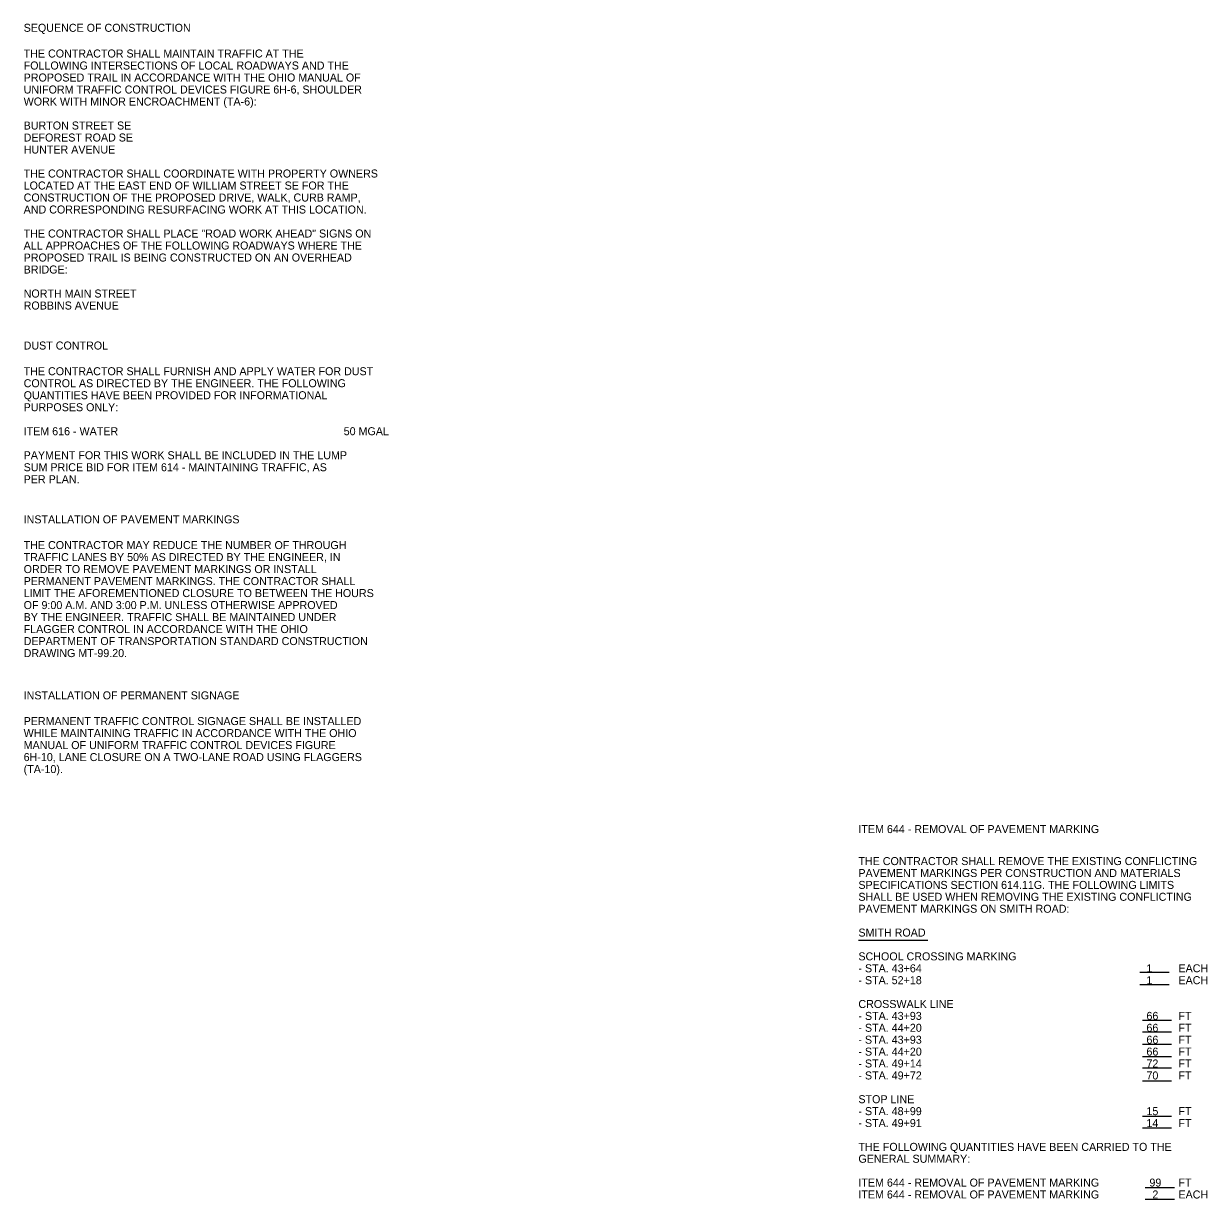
# Model space of a CAD drawing. Extents: x -39.4 to 36.9, y -12.9 to 28.
# Drawn here: x -39.35 to -18.64, y -12.34 to 8.24 of the extents above; entities that cross this region are included whole.
import ezdxf

# ---------------------------------------------------------------- set-up
doc = ezdxf.new("R2010")
doc.units = 0
for name, color, linetype in [('PM_P_Text', 7, 'Continuous'), ('SH_Text', 7, 'Continuous'), ('TX_P_1', 7, 'Continuous')]:
    doc.layers.add(name, color=color, linetype=linetype)

msp = doc.modelspace()

# ---------------------------------------------------------------- linework, layer by layer
at = {"layer": 'SH_Text'}
for p, q in [((-24.746, -7.803), (-23.532, -7.803)), ((-19.821, -8.364), (-19.31, -8.364)), ((-19.821, -8.577), (-19.31, -8.577)), ((-19.777, -9.2), (-19.266, -9.2)), ((-19.777, -9.409), (-19.266, -9.409)), ((-19.777, -9.621), (-19.266, -9.621)), ((-19.777, -9.841), (-19.266, -9.841)), ((-19.777, -10.039), (-19.266, -10.039)), ((-19.777, -10.263), (-19.266, -10.263)), ((-19.777, -10.881), (-19.266, -10.881)), ((-19.777, -11.088), (-19.266, -11.088)), ((-19.728, -12.131), (-19.217, -12.131)), ((-19.728, -12.338), (-19.217, -12.338))]:
    msp.add_line(p, q, dxfattribs=at)

# ---------------------------------------------------------------- texts
at = {"layer": 'PM_P_Text'}
for s, p in [('THE CONTRACTOR SHALL REMOVE THE EXISTING CONFLICTING', (-24.746, -6.489)), ('PAVEMENT MARKINGS PER CONSTRUCTION AND MATERIALS', (-24.746, -6.698)), ('SPECIFICATIONS SECTION 614.11G. THE FOLLOWING LIMITS', (-24.746, -6.906)), ('SHALL BE USED WHEN REMOVING THE EXISTING CONFLICTING', (-24.746, -7.114)), ('PAVEMENT MARKINGS ON SMITH ROAD:', (-24.746, -7.323)), ('SMITH ROAD', (-24.746, -7.74)), ('SCHOOL CROSSING MARKING', (-24.746, -8.156)), ('- STA. 43+64', (-24.746, -8.365)), ('1 ', (-19.706, -8.365)), ('EACH', (-19.146, -8.365)), ('- STA. 52+18', (-24.746, -8.573)), ('1 ', (-19.706, -8.573)), ('EACH', (-19.146, -8.573)), ('CROSSWALK LINE', (-24.746, -8.99)), ('- STA. 43+93', (-24.746, -9.198)), ('66 ', (-19.706, -9.198)), ('FT', (-19.146, -9.198)), ('- STA. 44+20', (-24.746, -9.406)), ('66', (-19.706, -9.406)), ('FT', (-19.146, -9.406)), ('- STA. 43+93', (-24.746, -9.615)), ('66 ', (-19.706, -9.615)), ('FT', (-19.146, -9.615)), ('- STA. 44+20', (-24.746, -9.823)), ('66 ', (-19.706, -9.823)), ('FT', (-19.146, -9.823)), ('- STA. 49+14 ', (-24.746, -10.031)), ('72', (-19.706, -10.031)), ('FT', (-19.146, -10.031)), ('- STA. 49+72', (-24.746, -10.24)), ('70 ', (-19.706, -10.24)), ('FT', (-19.146, -10.24)), ('STOP LINE', (-24.746, -10.656)), ('- STA. 48+99', (-24.746, -10.865)), ('15 ', (-19.706, -10.865)), ('FT', (-19.146, -10.865)), ('- STA. 49+91', (-24.746, -11.073)), ('14 ', (-19.706, -11.073)), ('FT', (-19.146, -11.073)), ('THE FOLLOWING QUANTITIES HAVE BEEN CARRIED TO THE ', (-24.746, -11.49)), ('GENERAL SUMMARY:', (-24.746, -11.698)), ('ITEM 644 - REMOVAL OF PAVEMENT MARKING', (-24.746, -12.115)), (' 99', (-19.706, -12.115)), ('FT', (-19.146, -12.115)), ('ITEM 644 - REMOVAL OF PAVEMENT MARKING', (-24.746, -12.323)), ('  2', (-19.706, -12.323)), ('EACH', (-19.146, -12.323))]:
    msp.add_text(s, height=0.14, dxfattribs=at).set_placement(p)
at = {"layer": 'SH_Text'}
msp.add_text('ITEM 644 - REMOVAL OF PAVEMENT MARKING', height=0.14, dxfattribs=at).set_placement((-24.746, -5.929))
at = {"layer": 'TX_P_1'}
for s, p in [('SEQUENCE OF CONSTRUCTION', (-39.352, 8.093)), ('THE CONTRACTOR SHALL MAINTAIN TRAFFIC AT THE ', (-39.352, 7.643)), ('FOLLOWING INTERSECTIONS OF LOCAL ROADWAYS AND THE ', (-39.352, 7.433)), ('PROPOSED TRAIL IN ACCORDANCE WITH THE OHIO MANUAL OF ', (-39.352, 7.223)), ('UNIFORM TRAFFIC CONTROL DEVICES FIGURE 6H-6, SHOULDER ', (-39.352, 7.013)), ('WORK WITH MINOR ENCROACHMENT (TA-6):', (-39.352, 6.803)), ('BURTON STREET SE', (-39.352, 6.383)), ('DEFOREST ROAD SE', (-39.352, 6.173)), ('HUNTER AVENUE', (-39.352, 5.963)), ('THE CONTRACTOR SHALL COORDINATE WITH PROPERTY OWNERS ', (-39.352, 5.543)), ('LOCATED AT THE EAST END OF WILLIAM STREET SE FOR THE ', (-39.352, 5.333)), ('CONSTRUCTION OF THE PROPOSED DRIVE, WALK, CURB RAMP, ', (-39.352, 5.123)), ('AND CORRESPONDING RESURFACING WORK AT THIS LOCATION.', (-39.352, 4.913)), ('THE CONTRACTOR SHALL PLACE "ROAD WORK AHEAD" SIGNS ON ', (-39.352, 4.493)), ('ALL APPROACHES OF THE FOLLOWING ROADWAYS WHERE THE ', (-39.352, 4.283)), ('PROPOSED TRAIL IS BEING CONSTRUCTED ON AN OVERHEAD ', (-39.352, 4.073)), ('BRIDGE:', (-39.352, 3.863)), ('NORTH MAIN STREET', (-39.352, 3.443)), ('ROBBINS AVENUE', (-39.352, 3.233)), ('DUST CONTROL', (-39.352, 2.533)), ('THE CONTRACTOR SHALL FURNISH AND APPLY WATER FOR DUST ', (-39.352, 2.083)), ('CONTROL AS DIRECTED BY THE ENGINEER. THE FOLLOWING ', (-39.352, 1.873)), ('QUANTITIES HAVE BEEN PROVIDED FOR INFORMATIONAL ', (-39.352, 1.663)), ('PURPOSES ONLY:', (-39.352, 1.453)), ('ITEM 616 - WATER', (-39.352, 1.033)), ('50 MGAL', (-33.752, 1.033)), ('PAYMENT FOR THIS WORK SHALL BE INCLUDED IN THE LUMP ', (-39.352, 0.613)), ('SUM PRICE BID FOR ITEM 614 - MAINTAINING TRAFFIC, AS ', (-39.352, 0.403)), ('PER PLAN.', (-39.352, 0.193)), ('INSTALLATION OF PAVEMENT MARKINGS', (-39.352, -0.509)), ('THE CONTRACTOR MAY REDUCE THE NUMBER OF THROUGH ', (-39.352, -0.959)), ('TRAFFIC LANES BY 50% AS DIRECTED BY THE ENGINEER, IN ', (-39.352, -1.169)), ('ORDER TO REMOVE PAVEMENT MARKINGS OR INSTALL ', (-39.352, -1.379)), ('PERMANENT PAVEMENT MARKINGS. THE CONTRACTOR SHALL ', (-39.352, -1.589)), ('LIMIT THE AFOREMENTIONED CLOSURE TO BETWEEN THE HOURS ', (-39.352, -1.799)), ('OF 9:00 A.M. AND 3:00 P.M. UNLESS OTHERWISE APPROVED ', (-39.352, -2.009)), ('BY THE ENGINEER. TRAFFIC SHALL BE MAINTAINED UNDER ', (-39.352, -2.219)), ('FLAGGER CONTROL IN ACCORDANCE WITH THE OHIO ', (-39.352, -2.429)), ('DEPARTMENT OF TRANSPORTATION STANDARD CONSTRUCTION ', (-39.352, -2.639)), ('DRAWING MT-99.20.', (-39.352, -2.849)), ('INSTALLATION OF PERMANENT SIGNAGE', (-39.352, -3.589)), ('PERMANENT TRAFFIC CONTROL SIGNAGE SHALL BE INSTALLED ', (-39.352, -4.039)), ('WHILE MAINTAINING TRAFFIC IN ACCORDANCE WITH THE OHIO ', (-39.352, -4.249)), ('MANUAL OF UNIFORM TRAFFIC CONTROL DEVICES FIGURE ', (-39.352, -4.459)), ('6H-10, LANE CLOSURE ON A TWO-LANE ROAD USING FLAGGERS ', (-39.352, -4.669)), ('(TA-10).', (-39.352, -4.879))]:
    msp.add_text(s, height=0.14, dxfattribs=at).set_placement(p)

doc.saveas('drawing.dxf')
